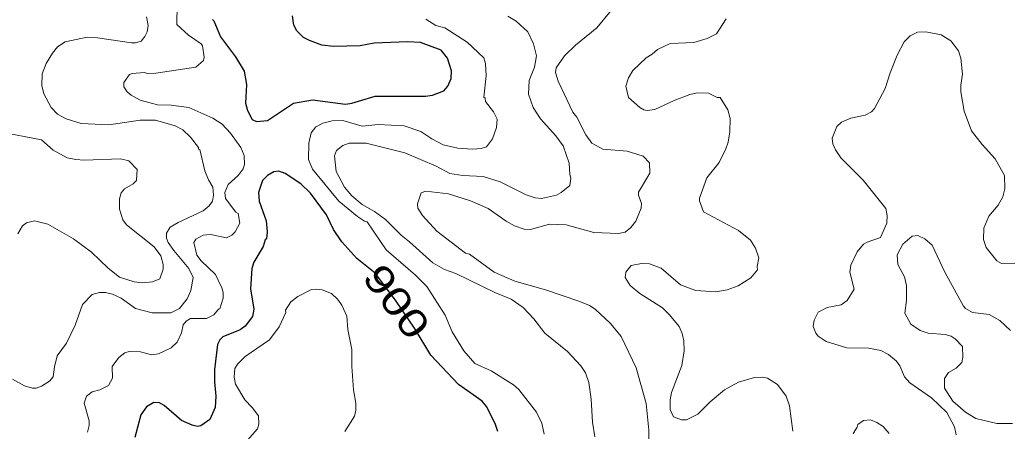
# Model space of a CAD drawing. Extents: x 447.8 to 473.9, y 7733.1 to 7760.8.
# Drawn here: x 453.231 to 456.079, y 7757.336 to 7758.518 of the extents above; entities that cross this region are included whole.
import ezdxf
from ezdxf.enums import TextEntityAlignment as Align

# ---------------------------------------------------------------- set-up
doc = ezdxf.new("R2010")
doc.units = 0
doc.header["$LTSCALE"] = 0.032
doc.layers.add('1', color=7, linetype='Continuous', lineweight=25)
doc.layers.add('2', color=7, linetype='Continuous', lineweight=13)
doc.layers.add('61', color=7, linetype='Continuous')

msp = doc.modelspace()

# ---------------------------------------------------------------- linework, layer by layer
at = {"layer": '1'}
for points in [[(453.7849, 7758.519), (453.789, 7758.5149), (453.8077, 7758.4691), (453.851, 7758.4114), (453.8762, 7758.3704), (453.8826, 7758.3323), (453.8802, 7758.2782), (453.8855, 7758.2571), (453.8995, 7758.2318), (453.912, 7758.2263), (453.943, 7758.2284), (454.0182, 7758.279), (454.0731, 7758.2878), (454.1672, 7758.276), (454.1861, 7758.2784), (454.253, 7758.299), (454.3976, 7758.2983), (454.4173, 7758.3021), (454.4503, 7758.3145), (454.4615, 7758.3275), (454.4716, 7758.3492), (454.4721, 7758.3714), (454.4611, 7758.4076), (454.4426, 7758.4306), (454.3828, 7758.4529), (454.3458, 7758.4553), (454.2496, 7758.4507), (454.2094, 7758.4433), (454.1329, 7758.4411), (454.099, 7758.4458), (454.0642, 7758.4584), (454.0467, 7758.4677), (454.0273, 7758.4863), (454.0186, 7758.5032), (454.015, 7758.5299)], [(454.6057, 7757.3348), (454.5976, 7757.3573), (454.5727, 7757.4066), (454.5609, 7757.4218), (454.4924, 7757.4697), (454.413, 7757.5537), (454.3678, 7757.6287), (454.3115, 7757.7118), (454.2524, 7757.7894), (454.2003, 7757.8323), (454.1573, 7757.8801), (454.1332, 7757.9155), (454.1131, 7757.9575), (454.0668, 7758.0196), (454.0392, 7758.0463), (453.9945, 7758.0763), (453.9757, 7758.0834), (453.9612, 7758.081), (453.9435, 7758.0706), (453.9287, 7758.0565), (453.9172, 7758.0215), (453.9188, 7757.9965), (453.9393, 7757.9399), (453.9427, 7757.909), (453.9405, 7757.8888), (453.9368, 7757.8854), (453.9312, 7757.8663), (453.9044, 7757.8216), (453.8986, 7757.8029), (453.8947, 7757.7448), (453.9042, 7757.6862), (453.9002, 7757.6654), (453.8786, 7757.6371), (453.8642, 7757.6266), (453.8146, 7757.6065), (453.8057, 7757.5984), (453.7994, 7757.585), (453.7912, 7757.5127), (453.7906, 7757.4776), (453.7944, 7757.4361), (453.7928, 7757.4038), (453.7774, 7757.3695), (453.7516, 7757.3508), (453.7415, 7757.3493), (453.7264, 7757.3527), (453.6956, 7757.3663), (453.6465, 7757.4093), (453.6322, 7757.4173), (453.6167, 7757.4182), (453.5951, 7757.4055), (453.5788, 7757.3825), (453.5622, 7757.3178)]]:
    msp.add_lwpolyline(points, dxfattribs=at)
at = {"layer": '2'}
for points in [[(453.6838, 7758.5609), (453.6828, 7758.5047), (453.7159, 7758.474), (453.7524, 7758.449), (453.756, 7758.443), (453.7608, 7758.4105), (453.759, 7758.4015), (453.7373, 7758.3825), (453.6226, 7758.3648), (453.5973, 7758.3641), (453.5892, 7758.3672), (453.5539, 7758.3643), (453.5466, 7758.3614), (453.53, 7758.3383), (453.53, 7758.3259), (453.5399, 7758.3117), (453.5513, 7758.3015), (453.5771, 7758.2868), (453.6265, 7758.2736), (453.6666, 7758.2726), (453.7175, 7758.2662), (453.7861, 7758.2358), (453.8127, 7758.2183), (453.8367, 7758.1927), (453.8664, 7758.1509), (453.8762, 7758.128), (453.877, 7758.1021), (453.8736, 7758.0896), (453.8591, 7758.0711), (453.8298, 7758.0447), (453.8205, 7758.0217), (453.8229, 7758.0044), (453.852, 7757.9651), (453.8585, 7757.9615), (453.8632, 7757.934), (453.8499, 7757.909), (453.8404, 7757.8994), (453.8249, 7757.8911), (453.7793, 7757.9007), (453.7583, 7757.8992), (453.7371, 7757.888), (453.7312, 7757.8779), (453.74, 7757.8415), (453.7527, 7757.8253)], [(453.5957, 7758.5272), (453.6005, 7758.5015), (453.5968, 7758.4837), (453.5908, 7758.4707), (453.5797, 7758.4572), (453.5641, 7758.452), (453.5519, 7758.4518), (453.4543, 7758.4667), (453.4245, 7758.4682), (453.3611, 7758.4551), (453.3395, 7758.4402), (453.3248, 7758.4223), (453.307, 7758.3926), (453.2956, 7758.3629), (453.2946, 7758.3298), (453.3002, 7758.3057), (453.3216, 7758.2657), (453.3398, 7758.2469), (453.3639, 7758.2339), (453.4079, 7758.2206), (453.4873, 7758.2166), (453.5768, 7758.2294), (453.6213, 7758.2301), (453.6777, 7758.2132), (453.7001, 7758.2017), (453.722, 7758.1807), (453.7445, 7758.1508), (453.7449, 7758.1461), (453.7486, 7758.145), (453.7628, 7758.0839), (453.7732, 7758.0578), (453.7856, 7758.0369), (453.788, 7758.0145), (453.7848, 7757.9964), (453.7758, 7757.9838), (453.7586, 7757.9693), (453.6863, 7757.9359), (453.6634, 7757.9225), (453.6526, 7757.9052), (453.6526, 7757.8906), (453.6575, 7757.8783), (453.6735, 7757.8547), (453.7175, 7757.8037), (453.7295, 7757.7777), (453.7227, 7757.7399), (453.7119, 7757.7164), (453.69, 7757.688), (453.6656, 7757.6755), (453.6114, 7757.6755), (453.5639, 7757.6881), (453.5229, 7757.7179), (453.4974, 7757.7293), (453.4773, 7757.7339), (453.4602, 7757.734), (453.4393, 7757.7289), (453.4115, 7757.7002)], [(454.3988, 7758.5199), (454.4272, 7758.5022), (454.4533, 7758.4954), (454.5169, 7758.4542), (454.5654, 7758.4087), (454.5705, 7758.3925), (454.5719, 7758.3576), (454.5654, 7758.296), (454.5688, 7758.2931), (454.5705, 7758.2839), (454.5934, 7758.2533), (454.6041, 7758.2331), (454.6017, 7758.2089), (454.5904, 7758.1765), (454.5729, 7758.153), (454.5577, 7758.1483), (454.5328, 7758.146), (454.4906, 7758.1491), (454.4482, 7758.1593), (454.4162, 7758.1757), (454.3844, 7758.1972), (454.3363, 7758.2133), (454.2613, 7758.2174), (454.2154, 7758.2126), (454.16, 7758.2285), (454.1292, 7758.2277), (454.1019, 7758.221), (454.0825, 7758.2107), (454.0687, 7758.1938), (454.0622, 7758.1633), (454.0607, 7758.1171), (454.0722, 7758.089), (454.1485, 7757.9971), (454.2016, 7757.9527), (454.2217, 7757.9396), (454.2302, 7757.9371), (454.2845, 7757.8572), (454.3687, 7757.7842), (454.401, 7757.7511), (454.4543, 7757.6695), (454.4746, 7757.621), (454.5075, 7757.5666), (454.539, 7757.53), (454.5861, 7757.5088), (454.651, 7757.4684), (454.6656, 7757.4552), (454.7172, 7757.3905), (454.7324, 7757.3585), (454.7387, 7757.3271)], [(454.6342, 7758.5291), (454.658, 7758.5145), (454.6921, 7758.4833), (454.7081, 7758.4494), (454.7171, 7758.4146), (454.7106, 7758.3817), (454.6955, 7758.3434), (454.6939, 7758.3044), (454.7073, 7758.2665), (454.7285, 7758.2339), (454.772, 7758.185), (454.7931, 7758.1559), (454.8108, 7758.1064), (454.8125, 7758.0742), (454.8157, 7758.0616), (454.8125, 7758.0421), (454.7878, 7758.0216), (454.7745, 7758.0141), (454.7314, 7758.005), (454.7132, 7758.0062), (454.6869, 7758.0148), (454.6123, 7758.052)], [(454.9311, 7758.5452), (454.8905, 7758.4957), (454.8291, 7758.4455), (454.7969, 7758.4143), (454.7728, 7758.3806), (454.7709, 7758.3669), (454.7787, 7758.3418), (454.8215, 7758.2529), (454.8329, 7758.2383), (454.8588, 7758.1879), (454.8754, 7758.1635), (454.9077, 7758.1466), (454.9776, 7758.1411)], [(454.9862, 7757.7543), (454.9713, 7757.7773), (454.9736, 7757.7932), (454.9887, 7757.8115), (455.019, 7757.8181), (455.0414, 7757.8166), (455.0753, 7757.8044), (455.1305, 7757.7559), (455.1748, 7757.7404), (455.2321, 7757.7364), (455.2649, 7757.742), (455.2968, 7757.7537), (455.3335, 7757.7765), (455.3523, 7757.7999), (455.3512, 7757.809), (455.3559, 7757.8336), (455.3465, 7757.8619), (455.3319, 7757.8847), (455.2979, 7757.9129), (455.1973, 7757.9658), (455.1853, 7757.9981), (455.1854, 7758.0059), (455.2067, 7758.0641), (455.2422, 7758.108), (455.2611, 7758.1469), (455.2676, 7758.1665), (455.2726, 7758.196), (455.2732, 7758.2348), (455.267, 7758.2595), (455.2453, 7758.2947), (455.2358, 7758.2952), (455.211, 7758.3078), (455.1793, 7758.3079), (455.1578, 7758.304), (455.1125, 7758.2864), (455.0571, 7758.2604), (455.0354, 7758.2575), (455.0256, 7758.2592), (455.0139, 7758.2662), (454.9811, 7758.295), (454.9737, 7758.3276), (454.981, 7758.3514), (454.9939, 7758.3723), (455.0325, 7758.4087), (455.0495, 7758.4192), (455.0647, 7758.4333), (455.1011, 7758.4505), (455.169, 7758.453), (455.2074, 7758.4645), (455.2344, 7758.4782), (455.262, 7758.5209)], [(456.0925, 7757.8182), (456.0537, 7757.8174), (456.0402, 7757.8257), (456.0099, 7757.8641), (456.0021, 7757.8863), (456.0026, 7757.9188), (456.0174, 7757.9539), (456.0445, 7757.9858), (456.058, 7758.0094), (456.0637, 7758.0321), (456.0629, 7758.0703), (456.0357, 7758.1187), (455.9978, 7758.1599), (455.968, 7758.199), (455.9469, 7758.2557), (455.9364, 7758.3108), (455.9364, 7758.3306), (455.9412, 7758.3618), (455.9373, 7758.4083), (455.9301, 7758.4291), (455.9077, 7758.4576), (455.8799, 7758.4754), (455.836, 7758.4842), (455.8125, 7758.4825), (455.7912, 7758.4722), (455.7744, 7758.4553), (455.7542, 7758.4168), (455.7338, 7758.3663), (455.7192, 7758.321), (455.6884, 7758.2636), (455.6796, 7758.254), (455.6615, 7758.2441), (455.621, 7758.2354), (455.5933, 7758.2237), (455.5805, 7758.2117), (455.5668, 7758.1781), (455.569, 7758.1613), (455.5765, 7758.1441), (455.592, 7758.121), (455.6563, 7758.0573), (455.7212, 7757.9754), (455.7246, 7757.9552), (455.7239, 7757.9334), (455.706, 7757.8928), (455.6672, 7757.8791), (455.6573, 7757.8728), (455.6391, 7757.8513), (455.6206, 7757.8132), (455.6173, 7757.7929), (455.63, 7757.7436), (455.6099, 7757.7109), (455.5926, 7757.6992), (455.5524, 7757.6915), (455.5269, 7757.6779), (455.5149, 7757.6545), (455.5123, 7757.6362), (455.5196, 7757.6178)], [(453.173, 7758.1966), (453.2933, 7758.1732), (453.327, 7758.1431), (453.3671, 7758.1218), (453.3917, 7758.1164), (453.4158, 7758.1148), (453.5203, 7758.1187), (453.5448, 7758.1124), (453.5684, 7758.0879), (453.5668, 7758.0566), (453.5566, 7758.0469), (453.5318, 7758.0321), (453.5227, 7758.0206), (453.5172, 7758.0033), (453.5181, 7757.9734), (453.5268, 7757.9432), (453.5382, 7757.9293), (453.6173, 7757.8654), (453.6365, 7757.8397), (453.6436, 7757.8148), (453.6437, 7757.8014), (453.6339, 7757.7734), (453.6121, 7757.7645), (453.5841, 7757.7621), (453.5601, 7757.7653), (453.5177, 7757.7783), (453.4853, 7757.8038), (453.4372, 7757.8499), (453.385, 7757.889), (453.3118, 7757.9312), (453.2734, 7757.9399), (453.2501, 7757.9342), (453.2389, 7757.9263), (453.2255, 7757.9026)], [(454.3382, 7758.1354), (454.2273, 7758.1636), (454.1783, 7758.1637), (454.1598, 7758.1567), (454.1419, 7758.1426), (454.136, 7758.127), (454.1405, 7758.0825), (454.1645, 7758.0375), (454.1862, 7758.0124), (454.2152, 7757.9872), (454.251, 7757.9674), (454.2821, 7757.9437), (454.3273, 7757.8993), (454.3518, 7757.8804), (454.4182, 7757.8197), (454.4523, 7757.8006), (454.4851, 7757.7886), (454.5971, 7757.7342), (454.6435, 7757.715), (454.6784, 7757.6916), (454.7088, 7757.6589), (454.7406, 7757.6175), (454.8055, 7757.5646), (454.8439, 7757.5237), (454.8577, 7757.5037), (454.8669, 7757.4758), (454.8735, 7757.4274), (454.8773, 7757.3615), (454.8846, 7757.3191)], [(454.6123, 7758.052), (454.5633, 7758.0675), (454.5046, 7758.0706), (454.4678, 7758.0766), (454.428, 7758.0977), (454.3382, 7758.1354)], [(454.9776, 7758.1411), (455.0239, 7758.1262), (455.0417, 7758.1072), (455.0425, 7758.0775), (455.0097, 7758.023), (455.0098, 7758.0142)], [(455.0098, 7758.0142), (455.0184, 7757.9904), (455.0181, 7757.9764), (455.002, 7757.939), (454.9882, 7757.921), (454.972, 7757.9073), (454.9523, 7757.904), (454.8814, 7757.9064), (454.8021, 7757.9288), (454.7544, 7757.9311), (454.6999, 7757.9152), (454.681, 7757.916), (454.6535, 7757.9257), (454.6294, 7757.9393), (454.5781, 7757.9754), (454.5274, 7757.9975), (454.4637, 7758.0176), (454.3988, 7758.0257), (454.3848, 7758.021), (454.3749, 7757.9892), (454.3752, 7757.977), (454.3888, 7757.9558), (454.4299, 7757.9106), (454.5126, 7757.8472), (454.5237, 7757.8445), (454.5954, 7757.7928), (454.6544, 7757.7666), (454.7424, 7757.7415), (454.8388, 7757.7097), (454.8696, 7757.6965), (454.8857, 7757.6864), (454.9294, 7757.645), (454.9599, 7757.6073), (455.0032, 7757.5175), (455.032, 7757.4156), (455.0401, 7757.3383), (455.0401, 7757.287)], [(456.0857, 7757.3573), (456.0402, 7757.3573), (455.9796, 7757.3718), (455.9502, 7757.3904), (455.914, 7757.4215), (455.8898, 7757.4594), (455.8899, 7757.4866), (455.9011, 7757.504), (455.9235, 7757.5166), (455.9401, 7757.5334), (455.9428, 7757.5488), (455.9417, 7757.5787), (455.9202, 7757.6009), (455.9087, 7757.6088), (455.8917, 7757.6137), (455.8427, 7757.617), (455.8195, 7757.6248), (455.7933, 7757.6436), (455.7755, 7757.6747), (455.7807, 7757.7109), (455.7808, 7757.7545), (455.775, 7757.7791), (455.7558, 7757.8151), (455.7536, 7757.8427), (455.7699, 7757.8731), (455.7972, 7757.8966), (455.8136, 7757.8981), (455.8329, 7757.8886), (455.854, 7757.8708), (455.8911, 7757.7931), (455.9441, 7757.695), (455.9503, 7757.6879), (455.97, 7757.677), (456.018, 7757.6706), (456.049, 7757.6534), (456.0801, 7757.6254)], [(453.7527, 7757.8253), (453.794, 7757.7863), (453.812, 7757.7476), (453.8153, 7757.7347), (453.8153, 7757.718), (453.8057, 7757.6871)], [(455.1356, 7757.6166), (455.1265, 7757.6363), (455.0992, 7757.6701), (455.0789, 7757.6904), (455.0139, 7757.7312), (454.9862, 7757.7543)], [(454.166, 7757.3343), (454.1932, 7757.3787), (454.1968, 7757.3958), (454.1968, 7757.4165), (454.1905, 7757.4547), (454.1857, 7757.5217), (454.1856, 7757.5707), (454.1745, 7757.6275), (454.1712, 7757.6666), (454.157, 7757.6974), (454.1443, 7757.7152), (454.1269, 7757.731), (454.1003, 7757.742), (454.0852, 7757.7443), (454.0693, 7757.7428), (454.0302, 7757.7227), (454.0105, 7757.707), (453.9951, 7757.6834), (453.9955, 7757.6771), (453.9769, 7757.6355), (453.9493, 7757.598), (453.8792, 7757.5502), (453.8583, 7757.5292), (453.849, 7757.5156), (453.8474, 7757.4907), (453.8516, 7757.4703), (453.8779, 7757.4253), (453.8996, 7757.4035), (453.9171, 7757.3792), (453.9181, 7757.3557), (453.914, 7757.3422), (453.8855, 7757.3096)], [(453.4115, 7757.7002), (453.3903, 7757.6407), (453.3648, 7757.5889), (453.3386, 7757.5519), (453.3304, 7757.521), (453.3273, 7757.4918)], [(453.8057, 7757.6871), (453.8021, 7757.6861), (453.7893, 7757.6705), (453.7681, 7757.6591), (453.7222, 7757.6595), (453.7092, 7757.6518), (453.7008, 7757.6413), (453.6957, 7757.6182), (453.683, 7757.5912), (453.6661, 7757.5755), (453.6302, 7757.5576), (453.6096, 7757.5553), (453.5784, 7757.5634), (453.5455, 7757.5648), (453.5328, 7757.5606), (453.5154, 7757.5476), (453.4964, 7757.5216), (453.4972, 7757.4878), (453.486, 7757.4672), (453.4612, 7757.4541), (453.4388, 7757.4487), (453.4227, 7757.4364), (453.4162, 7757.4165), (453.4305, 7757.3652), (453.4305, 7757.3521), (453.4257, 7757.3323)], [(455.4538, 7757.3355), (455.4446, 7757.408), (455.4343, 7757.436), (455.4098, 7757.4693), (455.3807, 7757.4883), (455.3661, 7757.491), (455.3438, 7757.4903), (455.2979, 7757.4765), (455.2571, 7757.4546), (455.2162, 7757.4203), (455.1809, 7757.3841), (455.1476, 7757.3677), (455.1337, 7757.3677), (455.1107, 7757.3766), (455.101, 7757.3977), (455.101, 7757.4261), (455.1046, 7757.4465), (455.1347, 7757.524), (455.1412, 7757.5667), (455.1404, 7757.5955), (455.1356, 7757.6166)], [(455.5196, 7757.6178), (455.5267, 7757.609), (455.5496, 7757.5938), (455.6093, 7757.5753), (455.6715, 7757.5738), (455.707, 7757.5672)], [(455.707, 7757.5672), (455.7288, 7757.5558), (455.7521, 7757.5365), (455.7616, 7757.5238), (455.7747, 7757.4917), (455.7905, 7757.4741), (455.8527, 7757.4311), (455.8967, 7757.3896), (455.9185, 7757.3479), (455.9234, 7757.3255)], [(453.3273, 7757.4918), (453.3165, 7757.4789), (453.2938, 7757.465), (453.2785, 7757.4591), (453.2671, 7757.4591), (453.2449, 7757.4661), (453.2104, 7757.4855)], [(455.7307, 7757.3289), (455.714, 7757.3487), (455.6957, 7757.3604), (455.6768, 7757.3683), (455.6574, 7757.366), (455.6408, 7757.355), (455.6389, 7757.347), (455.6273, 7757.3293)]]:
    msp.add_lwpolyline(points, dxfattribs=at)

# ---------------------------------------------------------------- texts
at = {"layer": '61', "width": 1.3}
msp.add_text('900', height=0.08, rotation=306.808, dxfattribs=at).set_placement((454.2822, 7757.6842), align=Align.CENTER)

doc.saveas('drawing.dxf')
